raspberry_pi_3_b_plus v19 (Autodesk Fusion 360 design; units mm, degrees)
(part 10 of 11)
sketch "Sketch2" plane through (0, 0, 6.23) normal (0, 0, 1) x axis (-1, 0, 0)
  line L1 (-6.7, -5.775) -> (-6.7, 5.775)
  line L2 (6.7, -5.775) -> (-6.7, -5.775)
  line L3 (6.7, 5.775) -> (6.7, -5.775)
  line L4 (-6.7, 5.775) -> (6.7, 5.775)
  line L5 (0, 7.5528) -> (0, 0)
  line L6 (2.2375, 4.5) -> (4.7625, 4.5)
  line L7 (2.5, 1.5) -> (2.2375, 4.5)
  line L8 (2.5, -0.5) -> (2.5, 1.5)
  line L9 (4.5, -0.5) -> (2.5, -0.5)
  line L10 (4.5, 1.5) -> (4.5, -0.5)
  line L11 (4.7625, 4.5) -> (4.5, 1.5)
  line L12 (3.5, 4.5) -> (3.5, -0.5)
  line L13 (-2.5, 1.5) -> (-2.2375, 4.5)
  line L14 (-2.5, -0.5) -> (-2.5, 1.5)
  line L15 (-4.5, -0.5) -> (-2.5, -0.5)
  line L16 (-4.5, 1.5) -> (-4.5, -0.5)
  line L17 (-4.7625, 4.5) -> (-4.5, 1.5)
  line L18 (-2.2375, 4.5) -> (-4.7625, 4.5)
  line L19 (7.5168, -5.775) -> (9.9907, -5.775)
  line L20 (7.65, -3.875) -> (7.65, -5.775)
  line L21 (4.8, -3.775) -> (7.55, -3.775)
  line L22 (-4.6, -5.275) -> (4.6, -5.275)
  line L23 (4.7, -3.875) -> (4.7, -5.175)
  line L24 (-7.65, -3.875) -> (-7.65, -5.775)
  line L25 (-4.8, -3.775) -> (-7.55, -3.775)
  line L26 (-4.7, -3.875) -> (-4.7, -5.175)
  line L27 (7.65, -5.775) -> (-7.65, -5.775)
  line L28 (2.15, -4) -> (2.85, -4)
  line L29 (1.75, -3.4) -> (1.75, -3.6)
  line L30 (2.85, -3) -> (2.15, -3)
  line L31 (3.25, -3.6) -> (3.25, -3.4)
  line L32 (3.25, -3.5) -> (1.75, -3.5)
  line L33 (-3.25, -3.6) -> (-3.25, -3.4)
  line L34 (-2.15, -4) -> (-2.85, -4)
  line L35 (-1.75, -3.4) -> (-1.75, -3.6)
  line L36 (-2.85, -3) -> (-2.15, -3)
  line L37 (-3.25, -3.5) -> (-1.75, -3.5)
  line L38 (9.9907, -5.775) -> (9.9907, 5.775)
  line L39 (18.4494, 5.775) -> (18.4494, -5.775)
  line L40 (18.4494, -1.55) -> (9.9907, -1.55)
  line L41 (-9.9907, -5.775) -> (-9.9907, 5.775)
  line L42 (-17.5994, -5.775) -> (-17.5994, 5.775)
  line L43 (-17.5994, -1.55) -> (-9.9907, -1.55)
  line L44 (-7.65, -5.775) -> (-17.5994, -5.775)
  line L45 (7.65, -5.775) -> (18.4494, -5.775)
  line L46 (-13.9907, 0.075) -> (-9.9907, 0.075)
  line L47 (-15.9907, 2.275) -> (-15.9907, -0.225)
  line L48 (-9.9907, 2.275) -> (-13.9907, 2.275)
  line L49 (-13.9907, -0.225) -> (-15.9907, -0.225)
  line L50 (-13.9907, 0.075) -> (-13.9907, -0.225)
  line L51 (-15.638, 4.275) -> (-15.9907, 2.275)
  line L52 (-14.3434, 4.275) -> (-15.638, 4.275)
  line L53 (-13.9907, 2.275) -> (-14.3434, 4.275)
  line L54 (13.9907, 0.075) -> (9.9907, 0.075)
  line L55 (13.9907, 0.075) -> (13.9907, -0.225)
  line L56 (13.9907, -0.225) -> (15.9907, -0.225)
  line L57 (15.9907, 2.275) -> (15.9907, -0.225)
  line L58 (15.638, 4.275) -> (15.9907, 2.275)
  line L59 (14.3434, 4.275) -> (15.638, 4.275)
  line L60 (13.9907, 2.275) -> (14.3434, 4.275)
  line L61 (9.9907, 2.275) -> (13.9907, 2.275)
  line L62 (-8.4, -3.775) -> (-8.4, -5.775)
  line L63 (-9.15, -5.775) -> (-9.15, -3.775)
  line L64 (8.4, -3.775) -> (8.4, -5.775)
  line L65 (9.15, -5.775) -> (9.15, -3.775)
  arc A1 centre (7.55, -3.875) radius 0.1 clockwise from (7.55, -3.775) to (7.65, -3.875)
  arc A2 centre (4.6, -5.175) radius 0.1 clockwise from (4.7, -5.175) to (4.6, -5.275)
  arc A3 centre (4.8, -3.875) radius 0.1 clockwise from (4.7, -3.875) to (4.8, -3.775)
  arc A4 centre (-7.55, -3.875) radius 0.1 clockwise from (-7.65, -3.875) to (-7.55, -3.775)
  arc A5 centre (-4.6, -5.175) radius 0.1 clockwise from (-4.6, -5.275) to (-4.7, -5.175)
  arc A6 centre (-4.8, -3.875) radius 0.1 clockwise from (-4.8, -3.775) to (-4.7, -3.875)
  arc A7 centre (2.85, -3.6) radius 0.4 clockwise from (3.25, -3.6) to (2.85, -4)
  arc A8 centre (2.15, -3.6) radius 0.4 clockwise from (2.15, -4) to (1.75, -3.6)
  arc A9 centre (2.15, -3.4) radius 0.4 clockwise from (1.75, -3.4) to (2.15, -3)
  arc A10 centre (2.85, -3.4) radius 0.4 clockwise from (2.85, -3) to (3.25, -3.4)
  arc A11 centre (-2.85, -3.4) radius 0.4 clockwise from (-3.25, -3.4) to (-2.85, -3)
  arc A12 centre (-2.85, -3.6) radius 0.4 clockwise from (-2.85, -4) to (-3.25, -3.6)
  arc A13 centre (-2.15, -3.6) radius 0.4 clockwise from (-1.75, -3.6) to (-2.15, -4)
  arc A14 centre (-2.15, -3.4) radius 0.4 clockwise from (-2.15, -3) to (-1.75, -3.4)
  arc A15 centre (-9.9907, -1.85) radius 0.3 clockwise from (-9.9907, -1.55) to (-9.9907, -2.15)
  arc A16 centre (9.9907, -1.85) radius 0.3 clockwise from (9.9907, -2.15) to (9.9907, -1.55)
  arc A17 centre (-9.9907, 0.375) radius 0.3 clockwise from (-9.9907, 0.675) to (-9.9907, 0.075)
  arc A18 centre (-9.9907, 1.975) radius 0.3 clockwise from (-9.9907, 2.275) to (-9.9907, 1.675)
  arc A19 centre (9.9907, 1.975) radius 0.3 clockwise from (9.9907, 1.675) to (9.9907, 2.275)
  arc A20 centre (9.9907, 0.375) radius 0.3 clockwise from (9.9907, 0.075) to (9.9907, 0.675)
  arc A21 centre (-8.775, -3.775) radius 0.375 clockwise from (-9.15, -3.775) to (-8.4, -3.775)
  arc A22 centre (8.775, -3.775) radius 0.375 clockwise from (8.4, -3.775) to (9.15, -3.775)
  point P1 (0, 0)
  point P6 (0, 0)
  point P14 (3.5, -0.5)
  point P15 (3.5, 4.5)
  point P10 (2.5, 1.5)
  point P13 (4.5, 1.5)
  point P8 (4.7625, 4.5)
  point P21 (-4.7625, 4.5)
  point P9 (2.2375, 4.5)
  point P16 (-2.2375, 4.5)
  point P17 (-2.5, 1.5)
  point P11 (2.5, -0.5)
  point P18 (-2.5, -0.5)
  point P12 (4.5, -0.5)
  point P19 (-4.5, -0.5)
  point P20 (-4.5, 1.5)
  point P24 (7.65, -5.775)
  point P28 (4.8, -3.775)
  point P34 (4.8, -3.775)
  point P36 (-7.65, -5.775)
  point P25 (7.65, -3.875)
  point P37 (-7.65, -3.875)
  point P26 (7.55, -3.775)
  point P39 (-7.55, -3.775)
  point P40 (-4.8, -3.775)
  point P29 (4.6, -5.275)
  point P44 (-4.6, -5.275)
  point P31 (4.7, -5.175)
  point P41 (-4.7, -5.175)
  point P33 (4.7, -3.875)
  point P42 (-4.7, -3.875)
  point P46 (-4.8, -3.775)
  point P30 (-4.6, -5.275)
  point P47 (3.25, -4)
  point P48 (1.75, -4)
  point P49 (3.25, -3)
  point P62 (1.75, -3.5)
  point P63 (3.25, -3.5)
  point P64 (2.5, -3.5)
  point P50 (2.85, -4)
  point P70 (-2.85, -4)
  point P51 (3.25, -3.6)
  point P68 (-3.25, -3.6)
  point P53 (2.15, -4)
  point P71 (-2.15, -4)
  point P54 (1.75, -3.6)
  point P73 (-1.75, -3.6)
  point P56 (1.75, -3.4)
  point P74 (-1.75, -3.4)
  point P57 (2.15, -3)
  point P76 (-2.15, -3)
  point P59 (2.85, -3)
  point P67 (-2.85, -3)
  point P60 (3.25, -3.4)
  point P66 (-3.25, -3.4)
  point P77 (-1.75, -3.5)
  point P78 (-3.25, -3.5)
  point P79 (-2.5, -3.5)
  point P84 (9.9907, -1.55)
  point P85 (18.4494, -1.55)
  point P90 (-9.9907, -1.55)
  point P91 (-17.5994, -1.55)
  point P92 (-9.9907, -2.15)
  point P96 (9.9907, -1.55)
  point P95 (9.9907, -2.15)
  point P89 (-17.5994, -5.775)
  point P97 (-17.5994, -5.775)
  point P82 (18.4494, -5.775)
  point P98 (18.4494, -5.775)
  point P99 (-9.9907, 0.075)
  point P101 (-9.9907, 2.275)
  point P104 (-13.9907, 0.075)
  point P107 (-13.9907, 2.275)
  point P100 (-15.9907, 2.275)
  point P108 (9.9907, 0.075)
  point P112 (15.9907, 2.275)
  point P116 (9.9907, 2.275)
  point P102 (-15.9907, -0.225)
  point P111 (15.9907, -0.225)
  point P103 (-13.9907, -0.225)
  point P110 (13.9907, -0.225)
  point P109 (13.9907, 0.075)
  point P105 (-15.638, 4.275)
  point P113 (15.638, 4.275)
  point P106 (-14.3434, 4.275)
  point P114 (14.3434, 4.275)
  point P115 (13.9907, 2.275)
  point P117 (-9.9907, 0.675)
  point P119 (-9.9907, 1.675)
  point P125 (9.9907, 0.075)
  point P123 (9.9907, 2.275)
  point P126 (9.9907, 0.675)
  point P122 (9.9907, 1.675)
  point P127 (-8.4, -5.775)
  point P131 (-9.15, -5.775)
  point P132 (8.4, -5.775)
  point P128 (-8.4, -3.775)
  point P133 (8.4, -3.775)
  point P129 (-9.15, -3.775)
  point P135 (9.15, -3.775)
  point P136 (9.15, -5.775)
  point P88 (-17.5994, 5.775)
  point P86 (-9.9907, 5.775)
  point P130 (-8.775, -3.775)
  coincident P1 P6
  vertical L5
  vertical L10
  horizontal L6
  vertical L8
  midpoint L9 P14
  midpoint L6 P15
  vertical L12
  horizontal L9
  symmetric P10 P13 L12
  symmetric L5 P8 P21
  symmetric L5 P9 P16
  symmetric L5 P10 P17
  symmetric L5 P11 P18
  symmetric L5 P12 P19
  symmetric L5 P13 P20
  coincident L19 P24
  tangent L20 A1
  tangent A1 L21
  horizontal L21
  vertical L20
  horizontal L22
  tangent L22 A2
  tangent L23 A3
  tangent A2 L23
  vertical L23
  coincident P28 P34
  tangent L21 A3
  equal A1 A3
  equal A2 A3
  symmetric L5 P24 P36
  symmetric L5 P25 P37
  symmetric L5 P26 P39
  symmetric L5 A1 A4
  symmetric L5 P28 P40
  symmetric L5 P29 P44
  symmetric L5 P31 P41
  symmetric L5 A2 A5
  symmetric L5 P33 P42
  symmetric L5 P34 P46
  symmetric L5 A3 A6
  coincident P30 P44
  horizontal L28
  vertical L29
  horizontal L30
  vertical L31
  coincident P47 L28
  coincident P47 L31
  tangent L28 A7
  tangent L31 A7
  coincident P48 L28
  coincident P48 L29
  tangent L28 A8
  tangent L29 A8
  equal A7 A8
  tangent L29 A9
  tangent L30 A9
  equal A7 A9
  coincident P49 L30
  coincident P49 L31
  tangent L30 A10
  tangent L31 A10
  equal A7 A10
  midpoint L29 P62
  midpoint L31 P63
  midpoint L32 P64
  symmetric L5 P50 P70
  symmetric L5 P51 P68
  symmetric L5 A7 A12
  symmetric L5 P53 P71
  symmetric L5 P54 P73
  symmetric L5 A8 A13
  symmetric L5 P56 P74
  symmetric L5 P57 P76
  symmetric L5 A9 A14
  symmetric L5 P59 P67
  symmetric L5 P60 P66
  symmetric L5 A10 A11
  midpoint L35 P77
  midpoint L33 P78
  midpoint L37 P79
  coincident L38 P84
  coincident L39 P85
  coincident L41 P90
  coincident L42 P91
  horizontal L43
  horizontal L40
  collinear L40 L43
  coincident L41 P92
  tangent L43 A15
  symmetric L5 P90 P96
  symmetric L5 P92 P95
  symmetric L5 A15 A16
  coincident P89 P97
  coincident P82 P98
  coincident L41 P99
  coincident L41 P101
  vertical L47
  horizontal L46
  horizontal L48
  horizontal L49
  vertical L50
  horizontal L52
  vertical P104 P107
  coincident P100 L48
  symmetric L5 P99 P108
  symmetric L5 P100 P112
  symmetric L5 P101 P116
  symmetric L5 P102 P111
  symmetric L5 P103 P110
  symmetric L5 P104 P109
  symmetric L5 P105 P113
  symmetric L5 P106 P114
  symmetric L5 P107 P115
  coincident L41 P117
  tangent L46 A17
  coincident L41 P119
  tangent L48 A18
  equal A15 A18
  equal A15 A17
  symmetric L5 P99 P125
  symmetric L5 P101 P123
  symmetric L5 P117 P126
  symmetric L5 A17 A20
  symmetric L5 P119 P122
  symmetric L5 A18 A19
  coincident L44 P127
  tangent L62 A21
  coincident L44 P131
  vertical L62
  vertical L63
  tangent A21 L63
  symmetric L5 P127 P132
  symmetric L5 P128 P133
  symmetric L5 P129 P135
  symmetric L5 A21 A22
  symmetric L5 P131 P136
  dimension "d22_8" distance L6 L9 = 5
  dimension "d23_8" distance L8 L10 = 2
  dimension "d24_8" angle L7 L8 = 5
  dimension "d25_8" distance P1 L12 = 3.5
  dimension "d26_5" distance P10 L9 = 2
  dimension "d27_7" distance P1 L9 = 0.5
  dimension "d28_7" distance L5 L20 = 7.65
  dimension "d29_7" radius A1 = 0.1
  dimension "d31_10" distance L2 L22 = 0.5
  dimension "d32_8" distance L2 L21 = 2
  dimension "d33_8" distance L3 L23 = 2
  dimension "d36_7" distance P47 P48 = 1.5
  dimension "d37_7" distance P47 P49 = 1
  dimension "d38_5" radius A7 = 0.4
  dimension "d39_6" distance P1 L32 = 3.5
  dimension "d40_7" distance P64 P79 = 5
  dimension "d51_4" distance P88 L43 = 7.325
  dimension "d52_7" radius A15 = 0.3
  dimension "d53_8" distance L46 L48 = 2.2
  dimension "d54_9" distance P86 L48 = 3.5
  dimension "d55_8" distance L41 L47 = 6
  dimension "d57_8" distance P102 P103 = 2
  dimension "d58_5" angle L47 L51 = 10
  dimension "d59_5" angle L48 L53 = 100
  dimension "d60_5" distance L48 L52 = 2
  dimension "d62_6" distance L46 L49 = 0.3
  dimension "d67_8" distance L24 L62 = 0.75
  dimension "d68_8" distance L62 L63 = 0.75
  dimension "d69_8" distance L44 P130 = 2
extrude "Extrude1" cut sketch "Sketch2" profile of L1 L2 L3 L6 L7 L8 L9 L10 L11 L13 L14 L15 L16 L17 L18 L19 L20 A1 L21 L22 A2 L23 A3 L24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 no distance stored
step "Refold1"
face "EdgeFlange2" FlangeHeight 2.5 named "d42_8" FlangeAngle 2 named "d43_6"
work_plane "WorkPlane1"
draft "Draft1" Angle1 5 named "d44_9" Angle2 5 named "d45_7"
face "EdgeFlange3" FlangeHeight 1 named "d46_7" FlangeAngle 20 named "d47_5"
face "EdgeFlange4" FlangeHeight 1 named "d48_6" FlangeAngle 45 named "d49_6"
fillet "Fillet1" radius 0.4 named "d50_3"
face "EdgeFlange5" FlangeHeight 5 named "d65_8" FlangeAngle 0 named "d66_7"
face "EdgeFlange7" FlangeHeight 2.25 named "d72_6" FlangeAngle 0 named "d73_7"
fillet "Fillet2" radius 0.25 named "d80_6"
face "EdgeFlange8" EdgeOffset_1 0 named "d75_6" EdgeOffset_2 -2.05 named "d76_6" FlangeHeight 2 named "d77_5" FlangeAngle 90 named "d78_5"
face "EdgeFlange9" EdgeOffset_1 0 named "d81_6" EdgeOffset_2 -1.65 named "d82_7" FlangeHeight 2.75 named "d83_7" FlangeAngle 0 named "d84_4"
face "EdgeFlange10" FlangeHeight 2.5 named "d85_2" FlangeAngle 0 named "d86_6"
face "EdgeFlange11" FlangeHeight 0.8 named "d87_6" FlangeAngle 20 named "d88_5"
face "EdgeFlange12" FlangeHeight 0.8 named "d89_7" FlangeAngle 40 named "d90_6"
mirror "Mirror1"
chamfer "Chamfer1" distance 0.2 named "d91_7"
remove_instance "RemoveInstance1"
work_plane "WorkPlane4" AlongDistance 5
sketch "Sketch2" plane through (0, 0, -5) normal (0, 0, -1) x axis (1, 0, 0)
  line L1 (-52.5, -26.75) -> (-52.5, 26.75)
  line L2 (40.5, 30.75) -> (-48.5, 30.75)
  line L3 (44.5, -26.75) -> (44.5, 26.75)
  line L4 (40.5, -30.75) -> (-48.5, -30.75)
  line L5 (44.5, 30.75) -> (-52.5, -30.75)
  line L6 (44.5, -30.75) -> (-52.5, 29.75)
  circle C1 centre (-39, 24.5) radius 2.5
  circle C2 centre (-39, -24.5) radius 2.5
  circle C3 centre (19, -24.5) radius 2.5
  circle C4 centre (19, 24.5) radius 2.5
  circle C5 centre (19, 24.5) radius 1.2
  circle C6 centre (19, -24.5) radius 1.2
  circle C7 centre (-39, -24.5) radius 1.2
  circle C8 centre (-39, 24.5) radius 1.2
  arc A1 centre (-48.5, -26.75) radius 4 clockwise from (-48.5, -30.75) to (-52.5, -26.75)
  arc A2 centre (-48.5, 26.75) radius 4 clockwise from (-52.5, 26.75) to (-48.5, 30.75)
  arc A3 centre (40.5, 26.75) radius 4 clockwise from (40.5, 30.75) to (44.5, 26.75)
  arc A4 centre (40.5, -26.75) radius 4 clockwise from (44.5, -26.75) to (40.5, -30.75)
  point P3 (-39, 24.5)
  point P4 (-39, 24.5)
  point P5 (-39, -24.5)
  point P6 (-39, -24.5)
  point P7 (19, -24.5)
  point P8 (19, -24.5)
  point P9 (19, 24.5)
  point P10 (19, 24.5)
  point P11 (19, 24.5)
  point P14 (-39, 24.5)
  point P15 (-52.5, -30.75)
  point P2 (-52.5, 29.75)
  point P16 (44.5, 30.75)
  point P17 (44.5, -30.75)
  coincident P3 P4
  coincident P5 P6
  coincident P7 P8
  coincident P9 P10
  coincident P10 P11
  concentric C3 C6
  concentric C2 C7
  coincident P4 P14
  perpendicular L1 L4
  perpendicular L2 L3
  horizontal L2
  coincident L1 P15
  coincident P15 L4
  tangent L1 A1
  tangent L4 A1
  coincident P2 L1
  tangent L1 A2
  tangent L2 A2
  coincident P16 L2
  coincident P16 L3
  tangent L2 A3
  tangent L3 A3
  coincident P17 L4
  coincident L3 P17
  tangent L4 A4
  tangent L3 A4
  dimension "d402" diameter C1 = 5
  dimension "d403" diameter C2 = 5
  dimension "d404" diameter C3 = 5
  dimension "d405" diameter C4 = 5
  dimension "d416" diameter C5 = 2.4
  dimension "d417" diameter C6 = 2.4
  dimension "d418" diameter C7 = 2.4
  dimension "d419" diameter C8 = 2.4
  dimension "d783" distance L1 L3 = 97
  dimension "d784" distance L2 L4 = 61.5
  dimension "d785" radius A1 = 4
  dimension "d786" radius A2 = 4
  dimension "d787" radius A3 = 4
  dimension "d788" radius A4 = 4
extrude "Extrude3" new body sketch "Sketch2" profile of C1 C2 C3 C4 C5 C6 C7 C8 against normal blind 14
shell "Shell1" innerThickness 1.5
work_plane "WorkPlane5" AlongDistance 0
sketch "Sketch3" plane through (-4, -29.25, 2.25) normal (0, 1, 0) x axis (1, 0, 0)
  line L1 (-22.9022, -6.7542) -> (-32.9022, -6.7542)
  line L2 (-22.9022, 2.2458) -> (-22.9022, -6.7542)
  line L3 (-32.9022, 2.2458) -> (-22.9022, 2.2458)
  line L4 (-32.9022, -6.7542) -> (-32.9022, 2.2458)
  line L5 (-22.9022, 2.2458) -> (-32.9022, -6.7542)
  line L6 (-32.9022, 2.2458) -> (-22.9022, -6.7542)
  line L7 (43.4, 0.65) -> (-35.4, 0.65)
  line L8 (-14.0578, -0.0561) -> (-14.0578, 2.6939)
  line L9
  line L10 (-15.5578, -6.75) -> (-14.0578, -6.75)
  line L11 (2.2124, -6.75) -> (-15.5578, -6.75)
  line L12 (2.2124, -3.2441) -> (2.2124, -6.75)
  line L13 (-15.5578, -3.2441) -> (2.2124, -3.2441)
  line L14 (-15.5578, -6.75) -> (-15.5578, -3.2441)
  line L15 (2.4402, -6.75) -> (-15.5578, -6.75)
  line L16 (2.4402, 2.25) -> (2.4402, -6.75)
  line L17 (-15.5578, 2.25) -> (2.4402, 2.25)
  line L18 (-15.5578, -6.75) -> (-15.5578, 2.25)
  line L19 (2.4402, -6.75) -> (-15.5578, -6.75)
  line L20 (20.1035, -7.35) -> (10.1035, -7.35)
  line L21 (20.1035, 2.65) -> (20.1035, -7.35)
  line L22 (10.1035, 2.65) -> (20.1035, 2.65)
  line L23 (10.1035, -7.35) -> (10.1035, 2.65)
  line L24 (20.1035, 2.65) -> (10.1035, -7.35)
  line L25 (10.1035, 2.65) -> (20.1035, -7.35)
  circle C1 centre (15.1035, -2.35) radius 5
  arc A1 centre (15.1035, -2.35) radius 1.5 clockwise from (14.1785, -3.5308) to (14.3535, -1.051)
  point P12 (-14.0578, 0.65)
  point P29 (15.1035, -2.35)
  point P24 (15.1035, -2.35)
  point P5 (-22.9022, 2.2458)
  point P6 (-32.9022, 2.2458)
  point P4 (-22.9022, -6.7542)
  point P13 (-14.0578, -6.75)
  point P14 (-15.5578, -6.75)
  point P18 (2.4402, -6.75)
  point P20 (-15.5578, 2.25)
  point P27 (20.1035, 2.65)
  point P28 (10.1035, 2.65)
  point P26 (20.1035, -7.35)
  horizontal L1
  parallel L1 L3
  parallel L2 L4
  perpendicular L1 L4
  coincident L7 P12
  coincident L8 P12
  perpendicular L9 L10
  horizontal L11
  vertical L12
  horizontal L13
  vertical L14
  horizontal L15
  vertical L16
  horizontal L17
  vertical L18
  concentric C1 A1
  horizontal L20
  perpendicular L20 L21
  parallel L20 L22
  parallel L21 L23
  coincident L24 P29
  coincident L25 P29
  coincident P24 P29
  dimension "d410" distance P5 P6 = 10
  dimension "d411" distance P4 P5 = 9
  dimension "d424" distance P13 P14 = 1.5
  dimension "d425" distance P14 P18 = 17.998
  dimension "d426" distance P14 P20 = 9
  dimension "d429" diameter C1 = 10
  dimension "d492" distance P27 P28 = 10
  dimension "d493" distance P26 P27 = 10
extrude "Extrude7" cut sketch "Sketch3" profile of L16 L17 L18 L19 against normal blind 1.5
extrude "Extrude8" cut sketch "Sketch3" profile of C1 L20 L21 L23 against normal blind 1.5
work_plane "WorkPlane6" AlongDistance 0
sketch "Sketch4" plane through (43, 0, 2.75) normal (-1, 0, 0) x axis (0, 1, 0)
  line L1 (-7.8856, -13.1329) -> (-26.8856, -13.1329)
  line L2 (6.3657, 1.1454) -> (-5.1343, 1.1454)
  line L3 (27.1157, -15.525) -> (-7.8856, -15.525)
  line L4 (27.1157, 1.975) -> (27.1157, -15.525)
  line L5 (-26.8856, 1.9671) -> (27.1157, 1.975)
  line L6 (-26.8856, -13.1329) -> (-26.8856, 1.9671)
  line L7 (-7.8856, -15.525) -> (-7.8856, -13.1329)
  point P3 (-26.8856, -13.1329)
  point P4 (-7.8856, -13.1329)
  point P2 (-26.8856, 1.9671)
  point P7 (27.1157, -15.525)
  point P8 (27.1157, 1.975)
  horizontal L3
  perpendicular L3 L4
  perpendicular L3 L7
  dimension "d433" distance P3 P4 = 19
  dimension "d434" distance P2 P3 = 15.1
  dimension "d454" distance P7 P8 = 17.5
work_plane "WorkPlane7" AlongDistance 0
sketch "Sketch5" plane through (-4, 0, 9) normal (0, 0, 1) x axis (1, 0, 0)
  line L1 (48.5, -26.75) -> (48.5, 26.75)
  line L2 (-48.5, 26.75) -> (-48.5, -26.75)
  line L3 (44.5, 30.75) -> (-44.5, 30.75)
  line L4 (48.5, -30.75) -> (48.5, 30.75)
  line L5 (44.5, -30.75) -> (-44.5, -30.75)
  arc A1 centre (-44.5, 26.75) radius 4 clockwise from (-48.5, 26.75) to (-44.5, 30.75)
  arc A2 centre (44.5, 26.75) radius 4 clockwise from (44.5, 30.75) to (48.5, 26.75)
  arc A3 centre (-44.5, -26.75) radius 4 clockwise from (-44.5, -30.75) to (-48.5, -26.75)
  arc A4 centre (44.5, -26.75) radius 4 clockwise from (48.5, -26.75) to (44.5, -30.75)
  point P3 (-48.5, 30.75)
  point P4 (48.5, 30.75)
  point P2 (-48.5, -30.75)
  point P5 (48.5, -30.75)
  vertical L1
  perpendicular L2 L3
  coincident P3 L2
  coincident P3 L3
  tangent L2 A1
  tangent L3 A1
  coincident P4 L3
  tangent L3 A2
  tangent L1 A2
  perpendicular L4 L5
  coincident P2 L5
  coincident P2 L2
  tangent L5 A3
  tangent L2 A3
  coincident P5 L5
  tangent L5 A4
  tangent L1 A4
  dimension "d789" distance P2 P3 = 61.5
  dimension "d790" radius A1 = 4
  dimension "d791" radius A2 = 4
  dimension "d792" radius A3 = 4
  dimension "d793" radius A4 = 4
extrude "Extrude9" new body sketch "Sketch5" profile of L1 along normal blind 11 bodies "Top"
shell "Shell2" innerThickness 1.5
work_plane "WorkPlane8" AlongDistance 0
sketch "Sketch6" plane through (-4, 0, 20) normal (0, 0, 1) x axis (1, 0, 0)
  line L1 (4.7829, -28.1511) -> (8.7829, -28.1511)
  line L2 (4.7829, -5.1511) -> (4.7829, -28.1511)
  line L3 (8.7829, -5.1511) -> (4.7829, -5.1511)
  line L4 (8.7829, -28.1511) -> (8.7829, -5.1511)
  line L5 (4.7829, -5.1511) -> (8.7829, -28.1511)
  line L6 (8.7829, -5.1511) -> (4.7829, -28.1511)
  line L7 (6.7829, -25.0511) -> (6.7829, -8.2511)
  point P6 (6.7829, -16.6511)
  point P4 (4.7829, -5.1511)
  point P5 (8.7829, -5.1511)
  point P3 (4.7829, -28.1511)
  horizontal L1
  perpendicular L1 L2
  parallel L1 L3
  parallel L2 L4
  coincident L5 P6
  coincident L6 P6
  midpoint P6 L7
  dimension "d456" distance P4 P5 = 4
  dimension "d457" distance P3 P4 = 23
extrude "Extrude11" cut sketch "Sketch6" profile of L1 L2 L3 L4 against normal blind 1.5
work_plane "WorkPlane9" AlongDistance -1.5
work_plane "WorkPlane10" AlongDistance 0.1
sketch "Sketch8" plane through (0, 0, 1.7) normal (0, 0, 1) x axis (1, 0, 0)
  circle C1 centre (-39, 24.5) radius 2.5
  circle C2 centre (19, 24.5) radius 2.5
  circle C3 centre (-39, -24.5) radius 2.5
  circle C4 centre (19, -24.5) radius 2.5
  point P2 (-39, 24.5)
  point P3 (-39, 24.5)
  point P4 (19, 24.5)
  point P5 (19, 24.5)
  point P6 (-39, -24.5)
  point P7 (-39, -24.5)
  point P8 (19, -24.5)
  point P9 (19, -24.5)
  coincident P2 P3
  coincident P4 P5
  coincident P6 P7
  coincident P8 P9
  dimension "d470" diameter C1 = 5
  dimension "d471" diameter C2 = 5
  dimension "d472" diameter C3 = 5
  dimension "d473" diameter C4 = 5
extrude "Extrude12" add sketch "Sketch8" no distance stored
work_plane "WorkPlane1"
sketch "Sketch1" plane through (-4, 0, 7.5) normal (0, 0, -1) x axis (1, 0, 0)
  line L1 (-44.5, -29.75) -> (44.5, -29.75)
  line L2 (70.0007, -34.75) -> (-39.9993, -34.75)
  line L3 (70.0007, -30.75) -> (70.0007, -34.75)
  line L4 (-39.9993, -30.75) -> (70.0007, -30.75)
  line L5 (-39.9993, -34.75) -> (-39.9993, -30.75)
  line L6 (-48.5, -25.75) -> (-48.5, 25.75)
  line L7 (-47, -25.75) -> (-47, 25.75)
  line L8 (-38.5, 0) -> (-48.5, 0)
  line L9 (48.5, -26.75) -> (48.5, 26.75)
  line L10 (48.5, 6.8843) -> (48.5, -8.1157)
  line L11 (38.5, 0) -> (48.5, 0)
  line L12 (-18.5, -34.75) -> (-38.5, -34.75)
  line L13 (-18.5, 10.25) -> (-18.5, -34.75)
  line L14 (-38.5, 10.25) -> (-18.5, 10.25)
  line L15 (-38.5, -34.75) -> (-38.5, 10.25)
  line L16 (18.5, -34.75) -> (38.5, -34.75)
  line L17 (18.5, 10.25) -> (18.5, -34.75)
  line L18 (38.5, 10.25) -> (18.5, 10.25)
  line L19 (38.5, -34.75) -> (38.5, 10.25)
  point P12 (-48.5, 0)
  point P18 (48.5, 0)
  point P24 (38.5, -34.75)
  point P2 (-39.9993, -34.75)
  point P5 (70.0007, -34.75)
  point P7 (-39.9993, -30.75)
  point P13 (-38.5, 0)
  point P19 (38.5, 0)
  point P20 (-38.5, -34.75)
  point P21 (-18.5, -34.75)
  point P23 (-38.5, 10.25)
  point P25 (18.5, -34.75)
  point P27 (38.5, 10.25)
  horizontal L2
  vertical L3
  horizontal L4
  vertical L5
  midpoint L6 P12
  perpendicular L7 L8
  midpoint L9 P18
  perpendicular L10 L11
  horizontal L12
  vertical L13
  horizontal L14
  vertical L15
  horizontal L16
  vertical L17
  horizontal L18
  vertical L19
  coincident L2 P24
  dimension "d496" distance P2 P5 = 110
  dimension "d497" distance P2 P7 = 4
  dimension "d498" distance P12 P13 = 10
  dimension "d499" distance P18 P19 = 10
  dimension "d500" distance P20 P21 = 20
  dimension "d501" distance P20 P23 = 45
  dimension "d502" distance P24 P25 = 20
  dimension "d503" distance P24 P27 = 45
extrude "Extrude1" new body sketch "Sketch1" profile of L1 L2 L3 L4 L5 L12 L13 L14 L15 L16 L17 L18 L19 against normal blind 24
work_plane "WorkPlane2" AlongDistance 0
sketch "Sketch2" plane through (-42.5, 10.25, 7.5) normal (-1, 0, 0) x axis (0, 1, 0)
  line L1 (19.5, -12.5) -> (15.5, -12.5)
  line L2 (15.5, -13.5) -> (15.5, -12.5)
  line L3 (20.5, -13.5) -> (-20.5, -13.5)
  line L4 (20.5, 0) -> (20.5, -24)
  line L5 (-20.5, 0) -> (-20.5, -24)
  line L6 (-20.5, -13.5) -> (20.5, -13.5)
  line L7 (-20.5, -17.5) -> (-20.5, -13.5)
  line L8 (20.5, -17.5) -> (-20.5, -17.5)
  line L9 (20.5, -13.5) -> (20.5, -17.5)
  line L10 (-20.5, -17.5) -> (20.5, -24)
  line L11 (-20.5, -24) -> (20.5, -24)
  point P2 (15.5, -12.5)
  point P5 (15.5, -12.5)
  point P7 (-20.5, -13.5)
  point P14 (-20.5, -17.5)
  point P9 (20.5, -24)
  point P16 (20.5, -24)
  point P11 (-20.5, -24)
  point P17 (-20.5, -24)
  point P6 (15.5, -13.5)
  point P8 (20.5, -13.5)
  point P15 (20.5, -17.5)
  coincident P2 P5
  perpendicular L1 L2
  horizontal L3
  coincident P7 L5
  horizontal L6
  vertical L7
  horizontal L8
  vertical L9
  coincident L5 P14
  coincident P9 P16
  coincident P11 P17
  dimension "d508" distance P5 P6 = 1
  dimension "d513" distance P8 P15 = 4
work_plane "WorkPlane3" AlongDistance 0
extrude "Extrude3" cut sketch "Sketch1" profile of L1 L13 L14 L15 L17 L18 L19 against normal blind 13.5
extrude "Extrude4" cut sketch "Sketch2" profile of L5 L10 L11 no distance stored
work_plane "WorkPlane4" AlongDistance 0
sketch "Sketch4" plane through (-32.5, -10.25, 23) normal (0, -1, 0) x axis (1, 0, 0)
  line L1 (-2, 8.5) -> (0, 8.5)
  line L2 (-2, 2) -> (-2, 8.5)
  line L3 (0, 2) -> (-2, 2)
  line L4 (0, 8.5) -> (0, 2)
  line L5 (10, 8.5) -> (-10, 8.5)
  line L6 (2, 8.5) -> (0, 8.5)
  line L7 (2, 2) -> (2, 8.5)
  line L8 (0, 2) -> (2, 2)
  line L9 (0, 8.5) -> (0, 2)
  line L10 (55, 8.5) -> (57, 8.5)
  line L11 (55, 2) -> (55, 8.5)
  line L12 (57, 2) -> (55, 2)
  line L13 (57, 8.5) -> (57, 2)
  line L14 (67, 8.5) -> (47, 8.5)
  line L15 (59, 8.5) -> (57, 8.5)
  line L16 (59, 2) -> (59, 8.5)
  line L17 (57, 2) -> (59, 2)
  line L18 (57, 8.5) -> (57, 2)
  line L19 (-2, 8.5) -> (-10, 8.5)
  line L20 (-2, 2) -> (-2, 8.5)
  line L21 (-10, 2) -> (-2, 2)
  line L22 (-10, 8.5) -> (-10, 2)
  line L23 (2, 8.5) -> (10, 8.5)
  line L24 (2, 2) -> (2, 8.5)
  line L25 (10, 2) -> (2, 2)
  line L26 (10, 8.5) -> (10, 2)
  line L27 (55, 8.5) -> (47, 8.5)
  line L28 (55, 2) -> (55, 8.5)
  line L29 (47, 2) -> (55, 2)
  line L30 (47, 8.5) -> (47, 2)
  line L31 (59, 8.5) -> (67, 8.5)
  line L32 (59, 2) -> (59, 8.5)
  line L33 (67, 2) -> (59, 2)
  line L34 (67, 8.5) -> (67, 2)
  point P2 (0, 8.5)
  point P11 (57, 8.5)
  point P6 (-10, 8.5)
  point P20 (-10, 8.5)
  point P7 (10, 8.5)
  point P23 (10, 8.5)
  point P15 (47, 8.5)
  point P26 (47, 8.5)
  point P16 (67, 8.5)
  point P29 (67, 8.5)
  point P3 (-2, 8.5)
  point P12 (55, 8.5)
  horizontal L1
  vertical L2
  horizontal L3
  vertical L4
  midpoint P2 L5
  horizontal L6
  vertical L7
  horizontal L8
  vertical L9
  horizontal L10
  vertical L11
  horizontal L12
  vertical L13
  midpoint P11 L14
  horizontal L15
  vertical L16
  horizontal L17
  vertical L18
  horizontal L19
  vertical L20
  horizontal L21
  vertical L22
  coincident P6 P20
  horizontal L23
  vertical L24
  horizontal L25
  vertical L26
  coincident P7 P23
  horizontal L27
  vertical L28
  horizontal L29
  vertical L30
  coincident P15 P26
  horizontal L31
  vertical L32
  horizontal L33
  vertical L34
  coincident P16 P29
  dimension "d521" distance P2 P3 = 2
  dimension "d522" distance P11 P12 = 2
extrude "Extrude5" cut sketch "Sketch4" profile of L2 L5 L7 L11 L14 L16 L19 L20 L21 L22 L23 L24 L25 L26 L27 L28 L29 L30 L31 L32 L33 L34 against normal blind 41
extrude "Extrude6" cut of existing geometry blind -1
sketch "Track" plane through (43, 0, 0) normal (-1, 0, 0) x axis (0, 1, 0)
  line L1 (-25.75, 0.7829) -> (-8.8843, 0.7829)
  line L2 (-25.75, -5) -> (-25.75, 0.7829)
  line L3 (25.75, -5) -> (-25.75, -5)
  line L4 (25.75, 0.775) -> (25.75, -5)
  line L5 (-8.8843, 0.775) -> (25.75, 0.775)
  line L6 (-8.8843, 0.7829) -> (-8.8843, 0.775)
  line L7 (-25.75, 20) -> (25.75, 20)
  line L8 (1.75, 20) -> (29.75, 20)
  line L9 (-1.25, 20) -> (1.75, 20)
  line L10 (3.75, 20) -> (1.75, 20)
  line L11 (1.75, 24) -> (1.75, 20)
  line L12 (-1.25, 20) -> (0.7792, 22.7056)
  line L13 (3.75, 20) -> (2.4736, 22.5528)
  line L14 (3.75, 20) -> (1.75, 20)
  line L15 (-26.75, 3.5) -> (26.75, 3.5)
  line L16 (-26.75, -9) -> (-26.75, 3.5)
  line L17 (26.75, -9) -> (-26.75, -9)
  line L18 (26.75, 3.5) -> (26.75, -9)
  arc A1 centre (1.5792, 22.1056) radius 1 clockwise from (0.7792, 22.7056) to (2.4736, 22.5528)
  point P9 (29.75, 20)
  point P12 (29.75, 20)
  point P16 (1.75, 24)
  point P13 (1.75, 20)
  point P14 (-1.25, 20)
  point P15 (3.75, 20)
  coincident P9 P12
  parallel L7 L8
  parallel L7 L9
  parallel L8 L10
  perpendicular L9 L11
  coincident P16 L12
  coincident P16 L13
  tangent L12 A1
  tangent L13 A1
  dimension "d527" distance P12 P13 = 28
  dimension "d528" distance P13 P14 = 3
  dimension "d529" distance P13 P15 = 2
  dimension "d530" distance P13 P16 = 4
  dimension "d531" radius A1 = 1
sketch "Sketch5" plane through (34.5, 0, 0) normal (1, 0, 0) x axis (0, 1, 0)
  line L1 (30.75, 21) -> (-10.25, 21)
  line L2 (30.75, 25) -> (30.75, 21)
  line L3 (-10.25, 25) -> (30.75, 25)
  line L4 (-10.25, 21) -> (-10.25, 25)
  line L5 (-1.25, 20) -> (1.75, 20)
  line L6 (3.75, 20) -> (1.75, 20)
  line L7 (3.75, 20) -> (2.4736, 22.5528)
  line L8 (1.75, 24) -> (1.75, 20)
  line L9 (-1.25, 20) -> (0.7792, 22.7056)
  line L10 (3.75, 20) -> (1.75, 20)
  arc A1 centre (1.5792, 22.1056) radius 1 clockwise from (0.7792, 22.7056) to (2.4736, 22.5528)
  point P11 (1.75, 24)
  point P10 (1.75, 20)
  point P12 (-1.25, 20)
  point P8 (3.75, 20)
  perpendicular L5 L8
  coincident P11 L9
  coincident P11 L7
  tangent L9 A1
  tangent L7 A1
  dimension "d567" distance P10 P12 = 3
  dimension "d568" distance P8 P10 = 2
  dimension "d569" distance P10 P11 = 4
  dimension "d570" radius A1 = 1
extrude "Extrude16" add of existing geometry blind 1
chamfer "Chamfer3" distance 2
sketch "Sketch6" plane through (-22.5, 0, 0) normal (1, 0, 0) x axis (0, 1, 0)
  line L1 (30.75, 21) -> (-10.25, 21)
  line L2 (30.75, 25) -> (30.75, 21)
  line L3 (-10.25, 25) -> (30.75, 25)
  line L4 (-10.25, 21) -> (-10.25, 25)
  line L5 (-1.25, 20) -> (1.75, 20)
  line L6 (3.75, 20) -> (1.75, 20)
  line L7 (3.75, 20) -> (2.4736, 22.5528)
  line L8 (1.75, 24) -> (1.75, 20)
  line L9 (-1.25, 20) -> (0.7792, 22.7056)
  line L10 (3.75, 20) -> (1.75, 20)
  arc A1 centre (1.5792, 22.1056) radius 1 clockwise from (0.7792, 22.7056) to (2.4736, 22.5528)
  point P11 (1.75, 24)
  point P10 (1.75, 20)
  point P12 (-1.25, 20)
  point P8 (3.75, 20)
  perpendicular L5 L8
  coincident P11 L9
  coincident P11 L7
  tangent L9 A1
  tangent L7 A1
  dimension "d571" distance P10 P12 = 3
  dimension "d572" distance P8 P10 = 2
  dimension "d573" distance P10 P11 = 4
  dimension "d574" radius A1 = 1
sketch "Sketch19" plane through (34.5, 0, 0) normal (1, 0, 0) x axis (0, 1, 0)
  line L1 (30.75, 25) -> (30.75, 21)
  line L2 (-10.25, 25) -> (30.75, 25)
  line L3 (-10.25, 21) -> (-10.25, 25)
  line L4 (30.75, 21) -> (-10.25, 21)
  line L5 (3.75, 20) -> (1.75, 20)
  line L6 (3.75, 20) -> (1.75, 20)
  line L7 (-1.25, 20) -> (1.75, 20)
  line L8 (1.75, 24) -> (1.75, 20)
  line L9 (3.75, 20) -> (2.4736, 22.5528)
  line L10 (-1.25, 20) -> (0.7792, 22.7056)
  line L11 (25.75, -5) -> (-25.75, -5)
  line L12 (1.75, -5) -> (1.75, 20)
  line L13 (-1.25, -5) -> (1.75, -5)
  line L14 (1.75, -9) -> (1.75, -5)
  line L15 (3.75, -5) -> (1.75, -5)
  line L16 (3.75, -5) -> (-1.25, -5)
  line L17 (2.4736, -7.5528) -> (3.75, -5)
  line L18 (-1.25, -5) -> (0.7792, -7.7056)
  line L19 (30.75, 21) -> (-10.25, 21)
  line L20 (30.75, 25) -> (30.75, 21)
  line L21 (-10.25, 25) -> (30.75, 25)
  line L22 (-10.25, 21) -> (-10.25, 25)
  arc A1 centre (1.5792, 22.1056) radius 1 clockwise from (0.7792, 22.7056) to (2.4736, 22.5528)
  arc A2 centre (1.5792, -7.1056) radius 1 clockwise from (2.4736, -7.5528) to (0.7792, -7.7056)
  point P12 (1.75, 24)
  point P16 (1.75, -5)
  point P18 (1.75, -9)
  point P11 (1.75, 20)
  point P13 (-1.25, 20)
  point P9 (3.75, 20)
  point P17 (-1.25, -5)
  point P19 (3.75, -5)
  perpendicular L7 L8
  coincident P12 L10
  coincident P12 L9
  tangent A1 L10
  tangent A1 L9
  coincident L11 P16
  perpendicular L5 L12
  perpendicular L12 L13
  perpendicular L13 L14
  perpendicular L12 L15
  coincident P18 L18
  coincident P18 L17
  tangent L18 A2
  tangent L17 A2
  dimension "d594" distance P11 P13 = 3
  dimension "d595" distance P9 P11 = 2
  dimension "d596" distance P11 P12 = 4
  dimension "d597" radius A1 = 1
  dimension "d639" distance P16 P17 = 3
  dimension "d640" distance P16 P18 = 4
  dimension "d641" distance P16 P19 = 2
  dimension "d642" radius A2 = 1
extrude "Extrude20" add sketch "Sketch19" profile of A1 L6 L7 L9 L10 against normal blind 20
extrude "Extrude21" cut of existing geometry blind -4
sketch "Sketch20" plane through (-22.5, 0, 0) normal (1, 0, 0) x axis (0, 1, 0)
  line L1 (30.75, 25) -> (30.75, 21)
  line L2 (-10.25, 25) -> (30.75, 25)
  line L3 (-10.25, 21) -> (-10.25, 25)
  line L4 (30.75, 21) -> (-10.25, 21)
  line L5 (3.75, 20) -> (1.75, 20)
  line L6 (3.75, 20) -> (1.75, 20)
  line L7 (-1.25, 20) -> (1.75, 20)
  line L8 (1.75, 24) -> (1.75, 20)
  line L9 (3.75, 20) -> (2.4736, 22.5528)
  line L10 (-1.25, 20) -> (0.7792, 22.7056)
  line L11 (1.75, -5) -> (1.75, 20)
  line L12 (-1.25, -5) -> (1.75, -5)
  line L13 (3.75, -5) -> (1.75, -5)
  line L14 (1.75, -9) -> (1.75, -5)
  line L15 (0.7792, -7.7056) -> (-1.25, -5)
  line L16 (3.75, -5) -> (2.4736, -7.5528)
  arc A1 centre (1.5792, 22.1056) radius 1 clockwise from (0.7792, 22.7056) to (2.4736, 22.5528)
  arc A2 centre (1.5792, -7.1056) radius 1 clockwise from (2.4736, -7.5528) to (0.7792, -7.7056)
  point P12 (1.75, 24)
  point P17 (1.75, -9)
  point P11 (1.75, 20)
  point P13 (-1.25, 20)
  point P9 (3.75, 20)
  point P14 (1.75, -5)
  point P15 (-1.25, -5)
  point P16 (3.75, -5)
  perpendicular L7 L8
  coincident P12 L10
  coincident P12 L9
  tangent A1 L10
  tangent A1 L9
  perpendicular L7 L11
  perpendicular L11 L12
  perpendicular L11 L13
  perpendicular L13 L14
  coincident P17 L15
  coincident P17 L16
  tangent L15 A2
  tangent L16 A2
  dimension "d602" distance P11 P13 = 3
  dimension "d603" distance P9 P11 = 2
  dimension "d604" distance P11 P12 = 4
  dimension "d605" radius A1 = 1
  dimension "d647" distance P14 P15 = 3
  dimension "d648" distance P14 P16 = 2
  dimension "d649" distance P14 P17 = 4
  dimension "d650" radius A2 = 1
extrude "Extrude22" add sketch "Sketch20" profile of A1 L6 L7 L9 L10 against normal blind 20
extrude "Extrude23" cut of existing geometry blind -4
extrude "Extrude9" cut sketch "Sketch5" profile of L1 L7 L9 A1 against normal blind 20
extrude "Extrude10" add sketch "Sketch5" profile of L1 L7 L9 A1 against normal blind 4
extrude "Extrude11" cut sketch "Sketch6" profile of L1 L7 L9 A1 against normal blind 20
extrude "Extrude12" add sketch "Sketch6" profile of L1 L7 L9 A1 against normal blind 4
chamfer "Chamfer1" distance 0.5
sketch "Sketch9" plane through (0, 30.75, 0) normal (0, -1, 0) x axis (1, 0, 0)
  line L1 (26.5, 25) -> (26.5, 30.5)
  line L2 (34.5, 25) -> (26.5, 25)
  line L3 (34.5, 21.5) -> (34.5, 25)
  line L4 (34, 21) -> (34.5, 21.5)
  line L5 (15, 21) -> (34, 21)
  line L6 (14.5, 21.5) -> (15, 21)
  line L7 (14.5, 25) -> (14.5, 21.5)
  line L8 (22.5, 25) -> (14.5, 25)
  line L9 (22.5, 30.5) -> (22.5, 25)
  line L10 (-30.5, 25) -> (-30.5, 30.5)
  line L11 (-22.5, 25) -> (-30.5, 25)
  line L12 (-22.5, 21.5) -> (-22.5, 25)
  line L13 (-23, 21) -> (-22.5, 21.5)
  line L14 (-42, 21) -> (-23, 21)
  line L15 (-42.5, 21.5) -> (-42, 21)
  line L16 (-42.5, 25) -> (-42.5, 21.5)
  line L17 (-34.5, 25) -> (-42.5, 25)
  line L18 (-34.5, 30.5) -> (-34.5, 25)
  line L19 (66.0007, 7.5) -> (-43.9993, 7.5)
  line L20 (48.0007, 7.5) -> (66.0007, 7.5)
  line L21 (48.0007, 29) -> (48.0007, 7.5)
  line L22 (66.0007, 29) -> (48.0007, 29)
  line L23 (66.0007, 7.5) -> (66.0007, 29)
  line L24 (-30.5, 30.5) -> (22.5, 30.5)
  line L25 (-43.9993, 30.5) -> (-34.5, 30.5)
  line L26 (-43.9993, 7.5) -> (-43.9993, 30.5)
  line L27 (66.0007, 30.5) -> (66.0007, 7.5)
  line L28 (26.5, 30.5) -> (66.0007, 30.5)
  circle C1 centre (48.0007, 29) radius 3.5
  point P30 (48.0007, 29)
  point P32 (48.0007, 29)
  horizontal L20
  vertical L21
  horizontal L22
  vertical L23
  coincident P30 P32
  dimension "d29" = 13.25 (= "d26")
  dimension "d29" = 13.25 (= "d26")
  dimension "d632" diameter C1 = 7
  dimension "d625" distance = 18
  dimension "d626" distance = 21.5
extrude "Extrude13" add sketch "Sketch9" profile of C1 against normal blind 4
hole "Hole1" HoleDepth 5.555 HoleDiameter 3 TipAngle 180 CSDiameter 5.5 CSAngle 90
work_plane "WorkPlane5"
mirror "Mirror2" mirrorStitchTolerance 0.1
extrude "Extrude24" add sketch "Sketch19" profile of L13 L14 L15 L16 L17 L18 A2 against normal blind 20
extrude "Extrude25" cut sketch "Sketch19" profile of L13 L14 L15 L16 L17 L18 A2 against normal blind 4
extrude "Extrude26" add sketch "Sketch20" profile of L12 L13 L14 L15 L16 A2 against normal blind 20
extrude "Extrude27" cut sketch "Sketch20" profile of L12 L13 L14 L15 L16 A2 against normal blind 4
sketch "Sketch2" plane through (0, 30.75, 0) normal (0, -1, 0) x axis (1, 0, 0)
  line L1 (57.8007, -15.5) -> (65.0007, -15.5)
  line L2 (57.8007, 28) -> (57.8007, -15.5)
  line L3 (65.0007, 28) -> (57.8007, 28)
  line L4 (65.0007, -15.5) -> (65.0007, 28)
  line L5 (57.8007, -15.5) -> (57.8007, 30.5)
  line L6 (66.0007, 33) -> (66.0007, -18)
  line L7 (-43.9993, -18) -> (-43.9993, 33)
  line L8 (-43.9993, 7.5) -> (66.0007, 7.5)
  line L9 (63.5742, 7.5) -> (60.6875, 2.5)
  line L10 (60.6875, 12.5) -> (63.5742, 7.5)
  line L11 (54.914, 12.5) -> (60.6875, 12.5)
  line L12 (52.0272, 7.5) -> (54.914, 12.5)
  line L13 (54.914, 2.5) -> (52.0272, 7.5)
  line L14 (60.6875, 2.5) -> (54.914, 2.5)
  line L15 (60.6875, -9.5) -> (54.914, -9.5)
  line L16 (63.5742, -4.5) -> (60.6875, -9.5)
  line L17 (60.6875, 0.5) -> (63.5742, -4.5)
  line L18 (57.8007, 16) -> (57.8007, -27.5)
  line L19 (54.914, 0.5) -> (60.6875, 0.5)
  line L20 (52.0272, -4.5) -> (54.914, 0.5)
  line L21 (54.914, -9.5) -> (52.0272, -4.5)
  line L22 (60.6875, 14.5) -> (54.914, 14.5)
  line L23 (63.5742, 19.5) -> (60.6875, 14.5)
  line L24 (60.6875, 24.5) -> (63.5742, 19.5)
  line L25 (57.8007, 40) -> (57.8007, -3.5)
  line L26 (54.914, 24.5) -> (60.6875, 24.5)
  line L27 (52.0272, 19.5) -> (54.914, 24.5)
  line L28 (54.914, 14.5) -> (52.0272, 19.5)
  line L29 (51.7385, -1) -> (53.4706, -2)
  line L30 (51.7385, 4) -> (53.4706, 5)
  line L31 (47.4084, 1.5) -> (51.7385, -1)
  line L32 (47.4084, 1.5) -> (51.7385, 4)
  line L33 (50.2952, 6.5) -> (53.1819, 1.5)
  line L34 (44.5217, 6.5) -> (50.2952, 6.5)
  line L35 (41.6349, 1.5) -> (44.5217, 6.5)
  line L36 (44.5217, -3.5) -> (41.6349, 1.5)
  line L37 (50.2952, -3.5) -> (44.5217, -3.5)
  line L38 (53.1819, 1.5) -> (50.2952, -3.5)
  line L39 (53.1819, 13.5) -> (50.2952, 8.5)
  line L40 (50.2952, 8.5) -> (44.5217, 8.5)
  line L41 (44.5217, 8.5) -> (41.6349, 13.5)
  line L42 (41.6349, 13.5) -> (44.5217, 18.5)
  line L43 (44.5217, 18.5) -> (50.2952, 18.5)
  line L44 (50.2952, 18.5) -> (53.1819, 13.5)
  line L45 (34.13, 2.5) -> (31.2432, 7.5)
  line L46 (39.9035, 24.5) -> (42.7902, 19.5)
  line L47 (34.13, 24.5) -> (39.9035, 24.5)
  line L48 (34.13, 12.5) -> (39.9035, 12.5)
  line L49 (20.8509, 13.5) -> (23.7377, 18.5)
  line L50 (34.13, -9.5) -> (31.2432, -4.5)
  line L51 (29.5112, -3.5) -> (23.7377, -3.5)
  line L52 (29.5112, 8.5) -> (23.7377, 8.5)
  line L53 (29.5112, 18.5) -> (32.3979, 13.5)
  line L54 (31.2432, 7.5) -> (34.13, 12.5)
  line L55 (31.2432, 19.5) -> (34.13, 24.5)
  line L56 (32.3979, 13.5) -> (29.5112, 8.5)
  line L57 (39.9035, 2.5) -> (34.13, 2.5)
  line L58 (23.7377, 8.5) -> (20.8509, 13.5)
  line L59 (39.9035, 14.5) -> (34.13, 14.5)
  line L60 (23.7377, -3.5) -> (20.8509, 1.5)
  line L61 (42.7902, 19.5) -> (39.9035, 14.5)
  line L62 (23.7377, 18.5) -> (29.5112, 18.5)
  line L63 (23.7377, 6.5) -> (29.5112, 6.5)
  line L64 (34.13, 0.5) -> (39.9035, 0.5)
  line L65 (42.7902, 7.5) -> (39.9035, 2.5)
  line L66 (29.5112, 6.5) -> (32.3979, 1.5)
  line L67 (31.2432, -4.5) -> (34.13, 0.5)
  line L68 (20.8509, 1.5) -> (23.7377, 6.5)
  line L69 (39.9035, -9.5) -> (34.13, -9.5)
  line L70 (39.9035, 12.5) -> (42.7902, 7.5)
  line L71 (42.7902, -4.5) -> (39.9035, -9.5)
  line L72 (32.3979, 1.5) -> (29.5112, -3.5)
  line L73 (34.13, 14.5) -> (31.2432, 19.5)
  line L74 (39.9035, 0.5) -> (42.7902, -4.5)
  line L75 (13.346, 2.5) -> (10.4592, 7.5)
  line L76 (19.1195, 24.5) -> (22.0062, 19.5)
  line L77 (13.346, 24.5) -> (19.1195, 24.5)
  line L78 (13.346, 12.5) -> (19.1195, 12.5)
  line L79 (0.0669, 13.5) -> (2.9537, 18.5)
  line L80 (13.346, -9.5) -> (10.4592, -4.5)
  line L81 (8.7272, -3.5) -> (2.9537, -3.5)
  line L82 (8.7272, 8.5) -> (2.9537, 8.5)
  line L83 (8.7272, 18.5) -> (11.6139, 13.5)
  line L84 (10.4592, 7.5) -> (13.346, 12.5)
  line L85 (10.4592, 19.5) -> (13.346, 24.5)
  line L86 (11.6139, 13.5) -> (8.7272, 8.5)
  line L87 (19.1195, 2.5) -> (13.346, 2.5)
  line L88 (2.9537, 8.5) -> (0.0669, 13.5)
  line L89 (19.1195, 14.5) -> (13.346, 14.5)
  line L90 (2.9537, -3.5) -> (0.0669, 1.5)
  line L91 (22.0062, 19.5) -> (19.1195, 14.5)
  line L92 (2.9537, 18.5) -> (8.7272, 18.5)
  line L93 (2.9537, 6.5) -> (8.7272, 6.5)
  line L94 (13.346, 0.5) -> (19.1195, 0.5)
  line L95 (22.0062, 7.5) -> (19.1195, 2.5)
  line L96 (8.7272, 6.5) -> (11.6139, 1.5)
  line L97 (10.4592, -4.5) -> (13.346, 0.5)
  line L98 (0.0669, 1.5) -> (2.9537, 6.5)
  line L99 (19.1195, -9.5) -> (13.346, -9.5)
  line L100 (19.1195, 12.5) -> (22.0062, 7.5)
  line L101 (22.0062, -4.5) -> (19.1195, -9.5)
  line L102 (11.6139, 1.5) -> (8.7272, -3.5)
  line L103 (13.346, 14.5) -> (10.4592, 19.5)
  line L104 (19.1195, 0.5) -> (22.0062, -4.5)
  line L105 (-7.438, 2.5) -> (-10.3248, 7.5)
  line L106 (-1.6645, 24.5) -> (1.2222, 19.5)
  line L107 (-7.438, 24.5) -> (-1.6645, 24.5)
  line L108 (-7.438, 12.5) -> (-1.6645, 12.5)
  line L109 (-20.7171, 13.5) -> (-17.8303, 18.5)
  line L110 (-7.438, -9.5) -> (-10.3248, -4.5)
  line L111 (-12.0568, -3.5) -> (-17.8303, -3.5)
  line L112 (-12.0568, 8.5) -> (-17.8303, 8.5)
  line L113 (-12.0568, 18.5) -> (-9.1701, 13.5)
  line L114 (-10.3248, 7.5) -> (-7.438, 12.5)
  line L115 (-10.3248, 19.5) -> (-7.438, 24.5)
  line L116 (-9.1701, 13.5) -> (-12.0568, 8.5)
  line L117 (-1.6645, 2.5) -> (-7.438, 2.5)
  line L118 (-17.8303, 8.5) -> (-20.7171, 13.5)
  line L119 (-1.6645, 14.5) -> (-7.438, 14.5)
  line L120 (-17.8303, -3.5) -> (-20.7171, 1.5)
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  point P11 (66.0007, 7.5)
  point P12 (-43.9993, 7.5)
  point P19 (57.8007, 7.5)
  point P36 (53.4706, -2)
  point P38 (53.4706, 5)
  point P40 (47.4084, 1.5)
  point P47 (47.4084, 1.5)
  point P222 (14.5, -7.7764)
  point P224 (14.5, -7.7764)
  point P227 (14.5, 22.7764)
  point P229 (14.5, 22.7764)
  point P238 (-42.5, 22.7764)
  point P240 (-42.5, 22.7764)
  point P247 (-42.5, -7.7764)
  point P249 (-42.5, -7.7764)
  point P2 (65.0007, -15.5)
  point P3 (57.8007, -15.5)
  point P37 (51.7385, -1)
  point P39 (51.7385, 4)
  point P256 (11.5, -11.75)
  point P257 (37.5, -11.75)
  point P255 (11.5, -3.75)
  point P261 (11.4704, 26.75)
  point P262 (37.4704, 26.75)
  point P260 (11.4704, 18.75)
  point P266 (-45.5, -11.75)
  point P267 (-19.5, -11.75)
  point P265 (-45.5, -3.75)
  point P271 (-45.5296, 26.75)
  point P272 (-19.5296, 26.75)
  point P270 (-45.5296, 18.75)
  horizontal L1
  vertical L2
  horizontal L3
  vertical L4
  vertical L5
  midpoint L6 P11
  midpoint L7 P12
  midpoint L5 P19
  midpoint L20 P36
  perpendicular L20 L29
  midpoint L13 P38
  perpendicular L13 L30
  perpendicular L20 L31
  perpendicular L13 L32
  coincident P40 P47
  coincident P222 P224
  coincident P227 P229
  coincident P238 P240
  coincident P247 P249
  dimension "d675" distance P2 P3 = 7.2
  dimension "d688" distance P19 L14 = 5
  dimension "d693" distance P36 P37 = 2
  dimension "d694" distance P38 P39 = 2
  dimension "d703" distance P256 P257 = 26
  dimension "d704" distance P255 P256 = 8
  dimension "d705" distance P261 P262 = 26
  dimension "d706" distance P260 P261 = 8
  dimension "d707" distance P266 P267 = 26
  dimension "d708" distance P265 P266 = 8
  dimension "d709" distance P271 P272 = 26
  dimension "d710" distance P270 P271 = 8
  dimension "d711" radius = 2
  dimension "d712" radius = 2
  dimension "d713" radius = 2
  dimension "d714" radius = 2
  dimension "d715" radius = 2
  dimension "d716" radius = 2
  dimension "d691" R-Pattern1-uDistance = 0
  dimension "d692" R-Pattern1-vDistance = 12
  dimension "d697" R-Pattern2-uDistance = 0
  dimension "d698" R-Pattern2-vDistance = 12
  dimension "d701" R-Pattern3-uDistance = -20.784
  dimension "d702" R-Pattern3-vDistance = 0
extrude "Extrude15" cut sketch "Sketch2" no distance stored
